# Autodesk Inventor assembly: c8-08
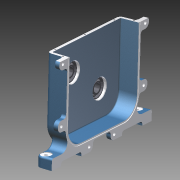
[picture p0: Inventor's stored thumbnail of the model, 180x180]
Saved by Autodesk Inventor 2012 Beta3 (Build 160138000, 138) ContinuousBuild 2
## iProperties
Created: 2011-01
Part Number: c8-08
Document SubType Name: Assembly
Designer: Beta-8540w
Author: Beta-8540w
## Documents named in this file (3)
- C:\Inventor 2012 Essentials\Assemblies\Chapter 8\c8-08.iam
- C:\Inventor 2012 Essentials\Parts\Chapter 8\c8-13.ipt
- C:\Inventor 2012 Essentials\Assemblies\Chapter 8\Design Accelerators\Bearing c8-02.iam
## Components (3 placed, 2 different names)
1. c8-13:1 — Insert:1, Insert:2
2. Bearing:1 [sub-assembly] — Insert:1
3. Bearing:2 [sub-assembly] — Insert:2
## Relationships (2: Insert 2)
- Insert:1: c8-13:1 ↔ Bearing:1
- Insert:2: c8-13:1 ↔ Bearing:2
